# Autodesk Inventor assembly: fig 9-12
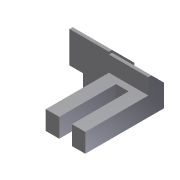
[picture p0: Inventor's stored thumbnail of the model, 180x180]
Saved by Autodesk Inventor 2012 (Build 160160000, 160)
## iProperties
Shininess: 64.0
Length Units: 11269
Angle Units: 11279
Time Units: 11290
Mass Units: 11283
Length Display Precision: 3
Angle Display Precision: 2
Created: 2002-01
Part Number: fig 9-12
Document SubType Name: Assembly
Designer: ***
Density: 0.0
Volumn: 0.0
Area: 0.0
PropertySet Name: Model Information
Control State: 0
Master: False
Checked Out: False
Author: ***
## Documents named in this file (3)
- C:\Users\CadCim\Documents\SAILESH\inventor-2011-fact-prt\c09_inv_2011-prt\c09_inv_2012_prt\fig 9-12.iam
- C:\Users\CadCim\Documents\SAILESH\inventor-2011-fact-prt\c09_inv_2011-prt\c09_inv_2012_prt\Part3.ipt
- C:\Users\CadCim\Documents\SAILESH\inventor-2011-fact-prt\c09_inv_2011-prt\c09_inv_2012_prt\Part4.ipt
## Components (2 placed, 2 different names)
1. Part3:1 — Flush:1, Flush:2, Flush:3, Mate:1
2. Part4:1 — Flush:1, Flush:2, Flush:3, Mate:1
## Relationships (4: Flush 3, Mate 1)
- Flush:1: Part3:1 ↔ Part4:1
- Flush:2: Part3:1 ↔ Part4:1
- Flush:3: Part3:1 ↔ Part4:1
- Mate:1: Part3:1 ↔ Part4:1
